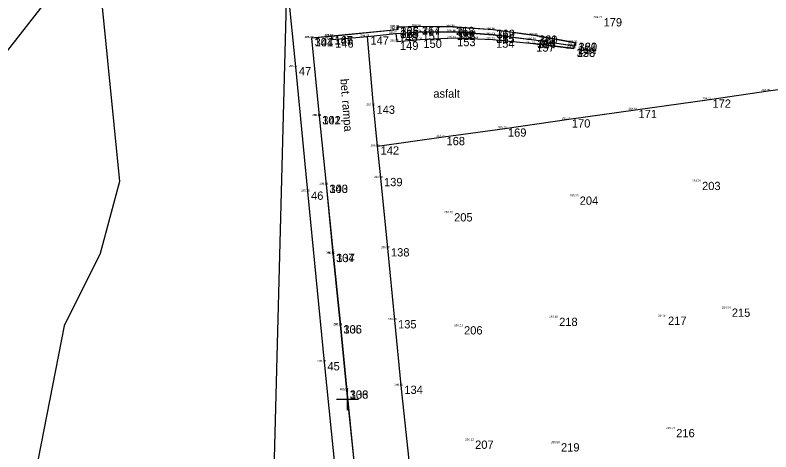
# Model space of a CAD drawing. Extents: x -594197 to -593885, y -1138044 to -1137704.
# Drawn here: x -594130.1 to -594061.7, y -1137904.8 to -1137865.2 of the extents above; entities that cross this region are included whole.
import ezdxf

# ---------------------------------------------------------------- set-up
doc = ezdxf.new("R2010")
doc.units = 0
for name, color, linetype in [('Katastrální mapa', 7, 'Continuous'), ('Podrobný bod', 7, 'Continuous'), ('Podrobný bod výška', 7, 'Continuous'), ('Podrobný bod číslo', 7, 'Continuous'), ('Polohopisné prvky', 7, 'Continuous'), ('Popisy', 7, 'Continuous'), ('Ram mapoveho listu', 7, 'Continuous'), ('Rozhraní ploch', 7, 'Continuous'), ('Čtvercová síť', 7, 'Continuous')]:
    doc.layers.add(name, color=color, linetype=linetype)

msp = doc.modelspace()

# ---------------------------------------------------------------- linework, layer by layer
at = {"layer": 'Katastrální mapa'}
for points in [[(-594122.72, -1137859.34), (-594120.63, -1137880.3), (-594122.39, -1137886.83), (-594125.63, -1137893.36), (-594128.54, -1137908.17), (-594123.89, -1137962.84)], [(-594122.72, -1137859.34), (-594105.5, -1137861.68), (-594106.87, -1137914.54), (-594112.21, -1137946.48), (-594118.04, -1137962.87), (-594123.89, -1137962.84)]]:
    msp.add_lwpolyline(points, dxfattribs=at)
at = {"layer": 'Podrobný bod'}
for p, q in [((-594077.12, -1137865.52), (-594077.12, -1137865.52)), ((-594095.52, -1137866.57), (-594095.52, -1137866.57)), ((-594095.51, -1137866.33), (-594095.51, -1137866.33)), ((-594095.51, -1137866.58), (-594095.51, -1137866.58)), ((-594095.5, -1137866.34), (-594095.5, -1137866.34)), ((-594093.56, -1137866.26), (-594093.56, -1137866.26)), ((-594093.56, -1137866.267), (-594093.56, -1137866.267)), ((-594090.47, -1137866.31), (-594090.47, -1137866.31)), ((-594090.47, -1137866.317), (-594090.47, -1137866.317)), ((-594086.82, -1137866.56), (-594086.82, -1137866.56)), ((-594086.82, -1137866.566), (-594086.82, -1137866.566)), ((-594101.46, -1137867.146), (-594101.46, -1137867.146)), ((-594101.45, -1137867.17), (-594101.45, -1137867.17)), ((-594098.21, -1137867.17), (-594098.21, -1137867.17)), ((-594095.63, -1137866.91), (-594095.63, -1137866.91)), ((-594093.49, -1137866.75), (-594093.49, -1137866.75)), ((-594090.401, -1137866.75), (-594090.401, -1137866.75)), ((-594090.4, -1137866.74), (-594090.4, -1137866.74)), ((-594086.84, -1137867.01), (-594086.84, -1137867.01)), ((-594086.84, -1137867.016), (-594086.84, -1137867.016)), ((-594082.97, -1137867.08), (-594082.97, -1137867.08)), ((-594082.97, -1137867.09), (-594082.97, -1137867.09)), ((-594103.26, -1137867.32), (-594103.26, -1137867.32)), ((-594103.25, -1137867.33), (-594103.25, -1137867.33)), ((-594101.4, -1137867.44), (-594101.4, -1137867.44)), ((-594095.54, -1137867.64), (-594095.54, -1137867.64)), ((-594093.42, -1137867.46), (-594093.42, -1137867.46)), ((-594090.37, -1137867.31), (-594090.37, -1137867.31)), ((-594086.85, -1137867.45), (-594086.85, -1137867.45)), ((-594083.22, -1137867.8), (-594083.22, -1137867.8)), ((-594083.12, -1137867.48), (-594083.12, -1137867.48)), ((-594083.12, -1137867.49), (-594083.12, -1137867.49)), ((-594079.393, -1137867.749), (-594079.393, -1137867.749)), ((-594079.38, -1137867.74), (-594079.38, -1137867.74)), ((-594079.555, -1137868.271), (-594079.555, -1137868.271)), ((-594079.55, -1137868.28), (-594079.55, -1137868.28)), ((-594079.461, -1137868.025), (-594079.461, -1137868.025)), ((-594079.456, -1137868.012), (-594079.456, -1137868.012)), ((-594079.45, -1137868.02), (-594079.45, -1137868.02)), ((-594104.68, -1137869.94), (-594104.68, -1137869.94)), ((-594061.95, -1137872.11), (-594061.95, -1137872.11)), ((-594097.66, -1137873.43), (-594097.66, -1137873.43)), ((-594067.27, -1137872.88), (-594067.27, -1137872.88)), ((-594073.96, -1137873.82), (-594073.96, -1137873.82)), ((-594102.57, -1137874.38), (-594102.57, -1137874.38)), ((-594102.56, -1137874.38), (-594102.56, -1137874.38)), ((-594079.99, -1137874.67), (-594079.99, -1137874.67)), ((-594085.77, -1137875.5), (-594085.77, -1137875.5)), ((-594091.33, -1137876.27), (-594091.33, -1137876.27)), ((-594097.29, -1137877.12), (-594097.29, -1137877.12)), ((-594096.98, -1137879.98), (-594096.98, -1137879.98)), ((-594101.92, -1137880.59), (-594101.92, -1137880.59)), ((-594101.92, -1137880.59), (-594101.92, -1137880.59)), ((-594068.21, -1137880.33), (-594068.21, -1137880.33)), ((-594103.58, -1137881.21), (-594103.58, -1137881.21)), ((-594079.28, -1137881.66), (-594079.28, -1137881.66)), ((-594090.64, -1137883.17), (-594090.64, -1137883.17)), ((-594096.35, -1137886.34), (-594096.35, -1137886.34)), ((-594101.32, -1137886.85), (-594101.32, -1137886.85)), ((-594101.3, -1137886.85), (-594101.3, -1137886.85)), ((-594065.52, -1137891.8), (-594065.52, -1137891.8)), ((-594071.29, -1137892.53), (-594071.29, -1137892.53)), ((-594095.71, -1137892.85), (-594095.71, -1137892.85)), ((-594081.14, -1137892.63), (-594081.14, -1137892.63)), ((-594100.66, -1137893.31), (-594100.66, -1137893.31)), ((-594100.65, -1137893.31), (-594100.65, -1137893.31)), ((-594089.74, -1137893.4), (-594089.74, -1137893.4)), ((-594102.1, -1137896.65), (-594102.1, -1137896.65)), ((-594100.08, -1137899.21), (-594100.08, -1137899.21)), ((-594100.07, -1137899.21), (-594100.07, -1137899.21)), ((-594095.14, -1137898.78), (-594095.14, -1137898.78)), ((-594070.55, -1137902.7), (-594070.55, -1137902.7)), ((-594088.74, -1137903.75), (-594088.74, -1137903.75)), ((-594080.97, -1137903.99), (-594080.97, -1137903.99))]:
    msp.add_line(p, q, dxfattribs=at)
at = {"layer": 'Polohopisné prvky'}
for points in [[(-594101.45, -1137867.17), (-594101.4, -1137867.44), (-594098.21, -1137867.17), (-594095.63, -1137866.91), (-594093.49, -1137866.75), (-594090.4, -1137866.74), (-594086.84, -1137867.01), (-594083.12, -1137867.48), (-594079.456, -1137868.012), (-594079.393, -1137867.749), (-594082.97, -1137867.09), (-594086.82, -1137866.566), (-594090.47, -1137866.317), (-594093.56, -1137866.267), (-594095.5, -1137866.34), (-594095.51, -1137866.58), (-594101.45, -1137867.17)], [(-594101.45, -1137867.17), (-594103.25, -1137867.33), (-594102.56, -1137874.38), (-594101.92, -1137880.59), (-594101.3, -1137886.85), (-594100.65, -1137893.31), (-594100.07, -1137899.21), (-594099.43, -1137905.61), (-594098.79, -1137912.19), (-594098.19, -1137918.04), (-594097.55, -1137919.91), (-594096.72, -1137925.69), (-594095.87, -1137931.77)]]:
    msp.add_lwpolyline(points, dxfattribs=at)
at = {"layer": 'Ram mapoveho listu'}
msp.add_line((-594002.411, -1137704.422), (-594196.548, -1137952.486), dxfattribs=at)
at = {"layer": 'Rozhraní ploch'}
for p, q in [((-594095.51, -1137866.58), (-594095.52, -1137866.57)), ((-594095.5, -1137866.34), (-594095.51, -1137866.33)), ((-594079.555, -1137868.271), (-594083.22, -1137867.8)), ((-594079.38, -1137867.74), (-594079.393, -1137867.749)), ((-594079.461, -1137868.025), (-594079.45, -1137868.02))]:
    msp.add_line(p, q, dxfattribs=at)
for points in [[(-594098.37, -1138025.23), (-594097.42, -1138020.88), (-594096.44, -1138015.16), (-594095.71, -1138009.9), (-594095.18, -1138005.26), (-594094.63, -1137998.75), (-594094.37, -1137992.38), (-594094.32, -1137983.2), (-594094.65, -1137973.95), (-594095.11, -1137967.54), (-594095.75, -1137960.98), (-594097.41, -1137943.93), (-594098.5, -1137932.77), (-594099.57, -1137922.21), (-594100.64, -1137910.93), (-594102.1, -1137896.65), (-594103.58, -1137881.21), (-594104.68, -1137869.94), (-594106.08, -1137856.13)], [(-594095.51, -1137866.33), (-594095.52, -1137866.57), (-594101.461, -1137867.146), (-594103.26, -1137867.32)], [(-594095.51, -1137866.33), (-594093.56, -1137866.26), (-594090.47, -1137866.31), (-594086.82, -1137866.56), (-594082.97, -1137867.08), (-594079.38, -1137867.74), (-594079.45, -1137868.02)], [(-594097.29, -1137877.12), (-594097.66, -1137873.43), (-594098.21, -1137867.17)], [(-594095.63, -1137866.91), (-594095.54, -1137867.64), (-594093.42, -1137867.46), (-594090.37, -1137867.31), (-594086.85, -1137867.45), (-594083.22, -1137867.8), (-594079.55, -1137868.28), (-594079.45, -1137868.02)], [(-594093.49, -1137866.75), (-594090.401, -1137866.75), (-594086.84, -1137867.016), (-594083.12, -1137867.49), (-594079.461, -1137868.025)], [(-594103.26, -1137867.32), (-594102.57, -1137874.38), (-594101.92, -1137880.59), (-594101.32, -1137886.85), (-594100.66, -1137893.31), (-594100.08, -1137899.21), (-594099.44, -1137905.61), (-594098.79, -1137912.19), (-594098.19, -1137918.04), (-594097.56, -1137919.91), (-594096.73, -1137925.69), (-594095.88, -1137931.78), (-594095.87, -1137931.77)], [(-594103.26, -1137867.32), (-594103.25, -1137867.33)], [(-594079.456, -1137868.012), (-594079.461, -1137868.025), (-594079.555, -1137868.271), (-594079.55, -1137868.28)], [(-594095.87, -1137931.77), (-594095.4, -1137931.77), (-594096.1, -1137925.58), (-594096.76, -1137919.76), (-594096.96, -1137917.93), (-594093.25, -1137917.65), (-594093.88, -1137911.39), (-594094.47, -1137905.26), (-594095.14, -1137898.78), (-594095.71, -1137892.85), (-594096.35, -1137886.34), (-594096.98, -1137879.98), (-594097.29, -1137877.12), (-594091.33, -1137876.27), (-594085.77, -1137875.5), (-594079.99, -1137874.67), (-594073.96, -1137873.82), (-594067.27, -1137872.88), (-594061.95, -1137872.11), (-594056.14, -1137871.3)]]:
    msp.add_lwpolyline(points, dxfattribs=at)
at = {"layer": 'Čtvercová síť'}
for p, q in [((-594100, -1137901), (-594100, -1137899)), ((-594101, -1137900), (-594099, -1137900))]:
    msp.add_line(p, q, dxfattribs=at)

# ---------------------------------------------------------------- texts
at = {"layer": 'Podrobný bod výška'}
for s, p in [('284.72 ', (-594077.745, -1137865.52)), ('285.04 ', (-594096.145, -1137866.57)), ('285.01 ', (-594096.135, -1137866.33)), ('286.50 ', (-594096.135, -1137866.58)), ('286.50 ', (-594096.125, -1137866.34)), ('284.84 ', (-594094.185, -1137866.26)), ('286.54 ', (-594094.185, -1137866.267)), ('286.54 ', (-594094.115, -1137866.75)), ('284.70 ', (-594091.095, -1137866.31)), ('286.30 ', (-594091.095, -1137866.318)), ('286.11 ', (-594091.026, -1137866.751)), ('286.30 ', (-594091.025, -1137866.74)), ('284.65 ', (-594087.445, -1137866.56)), ('286.01 ', (-594087.445, -1137866.566)), ('285.37 ', (-594103.885, -1137867.32)), ('286.67 ', (-594103.875, -1137867.33)), ('285.50 ', (-594102.086, -1137867.146)), ('286.63 ', (-594102.075, -1137867.17)), ('286.68 ', (-594102.025, -1137867.44)), ('286.69 ', (-594098.835, -1137867.17)), ('286.51 ', (-594096.255, -1137866.91)), ('286.38 ', (-594094.045, -1137867.46)), ('286.11 ', (-594090.995, -1137867.31)), ('285.73 ', (-594087.475, -1137867.45)), ('285.73 ', (-594087.465, -1137867.01)), ('286.01 ', (-594087.465, -1137867.016)), ('284.65 ', (-594083.595, -1137867.08)), ('285.71 ', (-594083.595, -1137867.09)), ('286.55 ', (-594096.165, -1137867.64)), ('285.31 ', (-594083.845, -1137867.8)), ('285.71 ', (-594083.745, -1137867.48)), ('285.31 ', (-594083.745, -1137867.49)), ('285.20 ', (-594080.086, -1137868.026)), ('285.50 ', (-594080.082, -1137868.012)), ('284.81 ', (-594080.075, -1137868.02)), ('285.50 ', (-594080.018, -1137867.749)), ('284.73 ', (-594080.005, -1137867.74)), ('285.20 ', (-594080.18, -1137868.271)), ('284.86 ', (-594080.175, -1137868.28)), ('285.37 ', (-594105.305, -1137869.94)), ('284.99 ', (-594062.575, -1137872.11)), ('284.91 ', (-594067.895, -1137872.88)), ('286.59 ', (-594098.285, -1137873.43)), ('284.86 ', (-594074.585, -1137873.82)), ('285.37 ', (-594103.195, -1137874.38)), ('286.64 ', (-594103.185, -1137874.38)), ('285.20 ', (-594080.615, -1137874.67)), ('285.75 ', (-594086.395, -1137875.5)), ('286.25 ', (-594091.955, -1137876.27)), ('286.59 ', (-594097.915, -1137877.12)), ('286.59 ', (-594097.605, -1137879.98)), ('284.70 ', (-594068.835, -1137880.33)), ('286.66 ', (-594102.545, -1137880.59)), ('285.35 ', (-594102.545, -1137880.59)), ('285.35 ', (-594104.205, -1137881.21)), ('285.25 ', (-594079.905, -1137881.66)), ('286.20 ', (-594091.265, -1137883.17)), ('286.59 ', (-594096.975, -1137886.34)), ('285.35 ', (-594101.945, -1137886.85)), ('286.66 ', (-594101.925, -1137886.85)), ('284.64 ', (-594066.145, -1137891.8)), ('285.46 ', (-594081.765, -1137892.63)), ('284.84 ', (-594071.915, -1137892.53)), ('285.35 ', (-594101.285, -1137893.31)), ('286.67 ', (-594101.275, -1137893.31)), ('286.56 ', (-594096.335, -1137892.85)), ('286.21 ', (-594090.365, -1137893.4)), ('285.37 ', (-594102.725, -1137896.65)), ('286.62 ', (-594095.765, -1137898.78)), ('285.37 ', (-594100.705, -1137899.21)), ('286.69 ', (-594100.695, -1137899.21)), ('284.74 ', (-594071.175, -1137902.7)), ('286.13 ', (-594089.365, -1137903.75)), ('285.50 ', (-594081.595, -1137903.99))]:
    msp.add_text(s, height=0.1875, dxfattribs=at).set_placement(p)
at = {"layer": 'Podrobný bod číslo'}
for s, p in [(' 179', (-594077.12, -1137866.27)), (' 325', (-594095.51, -1137867.33)), (' 326', (-594095.5, -1137867.09)), (' 166', (-594095.52, -1137867.32)), (' 165', (-594095.51, -1137867.08)), (' 317', (-594093.56, -1137867.017)), (' 164', (-594093.56, -1137867.01)), (' 318', (-594090.47, -1137867.068)), (' 163', (-594090.47, -1137867.06)), (' 319', (-594086.82, -1137867.316)), (' 162', (-594086.82, -1137867.31)), (' 167', (-594101.461, -1137867.896)), (' 145', (-594101.45, -1137867.92)), (' 147', (-594098.21, -1137867.92)), (' 148', (-594095.63, -1137867.66)), (' 151', (-594093.49, -1137867.5)), (' 316', (-594090.401, -1137867.501)), (' 152', (-594090.4, -1137867.49)), (' 315', (-594086.84, -1137867.76)), (' 155', (-594086.84, -1137867.766)), (' 320', (-594082.97, -1137867.84)), (' 161', (-594082.97, -1137867.83)), (' 301', (-594103.26, -1137868.07)), (' 144', (-594103.25, -1137868.08)), (' 146', (-594101.4, -1137868.19)), (' 149', (-594095.54, -1137868.39)), (' 150', (-594093.42, -1137868.21)), (' 153', (-594090.37, -1137868.06)), (' 154', (-594086.85, -1137868.2)), (' 157', (-594083.22, -1137868.55)), (' 314', (-594083.12, -1137868.24)), (' 156', (-594083.12, -1137868.23)), (' 321', (-594079.393, -1137868.499)), (' 160', (-594079.38, -1137868.49)), (' 323', (-594079.555, -1137869.021)), (' 158', (-594079.55, -1137869.03)), (' 324', (-594079.461, -1137868.776)), (' 322', (-594079.457, -1137868.762)), (' 159', (-594079.45, -1137868.77)), (' 47', (-594104.68, -1137870.69)), (' 143', (-594097.66, -1137874.18)), (' 172', (-594067.27, -1137873.63)), (' 171', (-594073.96, -1137874.57)), (' 302', (-594102.57, -1137875.13)), (' 141', (-594102.56, -1137875.13)), (' 170', (-594079.99, -1137875.42)), (' 169', (-594085.77, -1137876.25)), (' 168', (-594091.33, -1137877.02)), (' 142', (-594097.29, -1137877.87)), (' 139', (-594096.98, -1137880.73)), (' 303', (-594101.92, -1137881.34)), (' 140', (-594101.92, -1137881.34)), (' 203', (-594068.21, -1137881.08)), (' 46', (-594103.58, -1137881.96)), (' 204', (-594079.28, -1137882.41)), (' 205', (-594090.64, -1137883.92)), (' 138', (-594096.35, -1137887.09)), (' 304', (-594101.32, -1137887.6)), (' 137', (-594101.3, -1137887.6)), (' 215', (-594065.52, -1137892.55)), (' 217', (-594071.29, -1137893.28)), (' 135', (-594095.71, -1137893.6)), (' 218', (-594081.14, -1137893.38)), (' 305', (-594100.66, -1137894.06)), (' 136', (-594100.65, -1137894.06)), (' 206', (-594089.74, -1137894.15)), (' 45', (-594102.1, -1137897.4)), (' 306', (-594100.08, -1137899.96)), (' 133', (-594100.07, -1137899.96)), (' 134', (-594095.14, -1137899.53)), (' 216', (-594070.55, -1137903.45)), (' 207', (-594088.74, -1137904.5)), (' 219', (-594080.97, -1137904.74))]:
    msp.add_text(s, height=0.75, dxfattribs=at).set_placement(p)
at = {"layer": 'Popisy'}
for s, rotation, p in [('bet.', 357.57073, (-594089.81, -1137867.26)), ('bet. rampa', 274.41009, (-594100.65, -1137871.03))]:
    msp.add_text(s, height=0.75, rotation=rotation, dxfattribs=at).set_placement(p)
msp.add_text('asfalt', height=0.75, dxfattribs=at).set_placement((-594092.24, -1137872.72))

doc.saveas('drawing.dxf')
